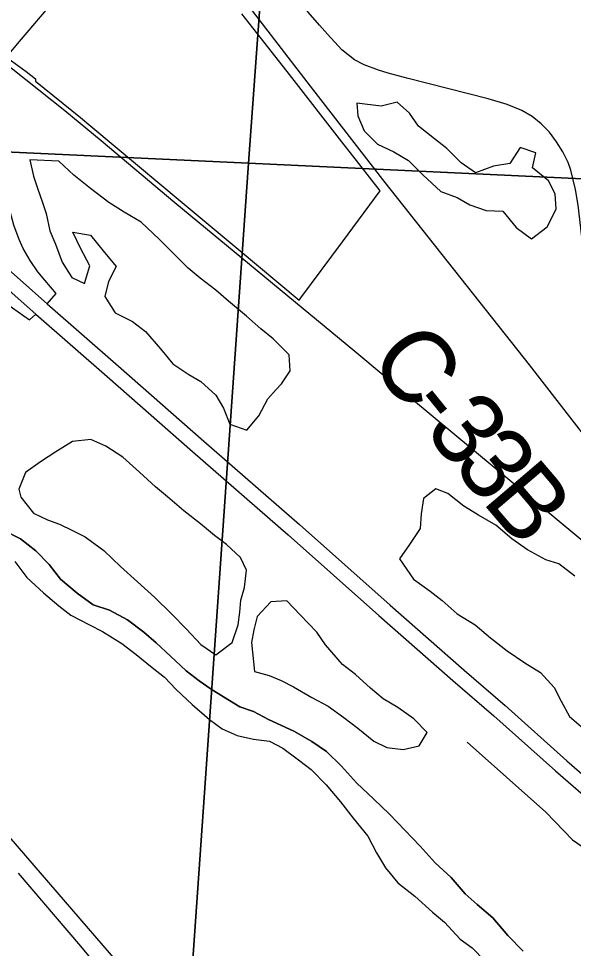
# Model space of a CAD drawing. Extents: x 39.8 to 73.8, y 13 to 35.
# Drawn here: x 44.259 to 44.694, y 30.521 to 31.251 of the extents above; entities that cross this region are included whole.
import ezdxf

# ---------------------------------------------------------------- set-up
doc = ezdxf.new("R2010")
doc.units = 0
for name, color, linetype in [('GM_X_Corporation', 7, 'Continuous'), ('GM_X_County_Road', 7, 'Continuous'), ('GM_X_County_Road_Text', 7, 'Continuous'), ('GM_X_Interchange_Ramps', 7, 'Continuous'), ('GM_X_Major_River', 7, 'Continuous'), ('GM_X_Minor_Lake', 7, 'Continuous'), ('GM_X_Rail_Line', 7, 'Continuous'), ('GM_X_State_Route', 7, 'Continuous'), ('GM_X_Township_Road', 7, 'Continuous'), ('GM_X_US_Route', 7, 'Continuous')]:
    doc.layers.add(name, color=color, linetype=linetype)

msp = doc.modelspace()

# ---------------------------------------------------------------- linework, layer by layer
at = {"layer": 'GM_X_Corporation'}
for points in [[(43.50363, 32.26026), (44.51605, 32.19572), (44.4392, 31.1377), (43.42824, 31.18464), (43.49688, 32.17123)], [(44.51605, 32.19572), (45.50689, 32.1262), (45.43139, 31.091), (44.4392, 31.1377)], [(44.4392, 31.1377), (44.36734, 30.10866), (43.36036, 30.17646), (43.42824, 31.18464)], [(45.43139, 31.091), (45.35678, 30.04923), (44.36734, 30.10866), (44.4392, 31.1377)]]:
    msp.add_lwpolyline(points, close=True, dxfattribs=at)
msp.add_lwpolyline([(44.17707, 31.26999), (44.23303, 31.23243), (44.26496, 31.20945), (44.27231, 31.20378), (44.27217, 31.20187), (44.30749, 31.17336), (44.31561, 31.16658), (44.38727, 31.10671), (44.43102, 31.07018), (44.47903, 31.0301), (44.48032, 31.03184), (44.51303, 31.076), (44.54253, 31.11582), (44.51915, 31.14584), (44.5144, 31.15194), (44.46948, 31.20962), (44.44265, 31.24369), (44.43396, 31.25472)], dxfattribs=at)
at = {"layer": 'GM_X_County_Road'}
for points in [[(44.25953, 31.23301), (44.2882, 31.26678), (44.30366, 31.27984), (44.31779, 31.28918), (44.33726, 31.29664), (44.35158, 31.30122), (44.36383, 31.30637), (44.37225, 31.31051), (44.38867, 31.31823)], [(44.44218, 31.25711), (44.48765, 31.1981), (44.54613, 31.12252), (44.65928, 30.97939), (44.71463, 30.90824), (44.72644, 30.89333), (44.75886, 30.855), (44.81526, 30.79658), (44.87483, 30.74254), (44.90837, 30.71525), (44.94666, 30.68662), (45.0573, 30.60034), (45.14776, 30.53069), (45.1864, 30.49736), (45.21018, 30.47485), (45.25625, 30.41816)], [(44.21891, 31.18513), (44.23311, 31.20197), (44.24725, 31.21855), (44.25953, 31.23301)], [(44.61064, 30.68328), (44.67255, 30.62834), (44.69344, 30.6067), (44.7068, 30.59748), (44.71696, 30.59428), (44.72881, 30.59033), (44.74085, 30.5845), (44.74894, 30.57791), (44.87201, 30.46877), (44.92544, 30.41816), (44.95724, 30.38297), (44.98791, 30.34666), (45.02367, 30.29961), (45.05979, 30.24561), (45.07504, 30.22002), (45.10608, 30.1647), (45.11907, 30.13967), (45.18154, 30.00363), (45.19396, 29.97672), (45.2075, 29.95264), (45.22124, 29.9342), (45.23479, 29.91726), (45.25379, 29.89788)]]:
    msp.add_lwpolyline(points, dxfattribs=at)
at = {"layer": 'GM_X_Interchange_Ramps'}
msp.add_lwpolyline([(44.28144, 31.02734), (44.2885, 31.03537), (44.27942, 31.04567), (44.27413, 31.05242), (44.26795, 31.06133), (44.26264, 31.07066), (44.25934, 31.0777), (44.25532, 31.0889), (44.25116, 31.10355), (44.24692, 31.11811), (44.24302, 31.13979), (44.2408, 31.15126), (44.23811, 31.15978), (44.23528, 31.16535), (44.22891, 31.17455), (44.22292, 31.18124), (44.21891, 31.18513)], dxfattribs=at)
at = {"layer": 'GM_X_Major_River'}
for p, q in [((44.26036, 30.84282), (44.24708, 30.8496)), ((44.27252, 30.83337), (44.26036, 30.84282)), ((44.28279, 30.82278), (44.27252, 30.83337)), ((44.25589, 30.82497), (44.26541, 30.81249)), ((44.29192, 30.81105), (44.28279, 30.82278)), ((44.26541, 30.81249), (44.27834, 30.80039)), ((44.30484, 30.80009), (44.29192, 30.81105)), ((44.27834, 30.80039), (44.2905, 30.79018)), ((44.31738, 30.79103), (44.30484, 30.80009)), ((44.2905, 30.79018), (44.3, 30.78301)), ((44.33027, 30.78689), (44.31738, 30.79103)), ((44.3, 30.78301), (44.31442, 30.77546)), ((44.34431, 30.77935), (44.33027, 30.78689)), ((44.31442, 30.77546), (44.32466, 30.77019)), ((44.35723, 30.76953), (44.34431, 30.77935)), ((44.32466, 30.77019), (44.33985, 30.76075)), ((44.36673, 30.76121), (44.35723, 30.76953)), ((44.33985, 30.76075), (44.35125, 30.75206)), ((44.37814, 30.75063), (44.36673, 30.76121)), ((44.35125, 30.75206), (44.36379, 30.74186)), ((44.3903, 30.73929), (44.37814, 30.75063)), ((44.36379, 30.74186), (44.37329, 30.7343)), ((44.40056, 30.73135), (44.3903, 30.73929)), ((44.37329, 30.7343), (44.38242, 30.72447)), ((44.41005, 30.72493), (44.40056, 30.73135)), ((44.38242, 30.72447), (44.39496, 30.71274)), ((44.41955, 30.71889), (44.41005, 30.72493)), ((44.43246, 30.71097), (44.41955, 30.71889)), ((44.39496, 30.71274), (44.40864, 30.70103)), ((44.44308, 30.70721), (44.43246, 30.71097)), ((44.45484, 30.70117), (44.44308, 30.70721)), ((44.40864, 30.70103), (44.41852, 30.69385)), ((44.4647, 30.69665), (44.45484, 30.70117)), ((44.47533, 30.69176), (44.4647, 30.69665)), ((44.41852, 30.69385), (44.43028, 30.68858)), ((44.43028, 30.68858), (44.44317, 30.68559)), ((44.48899, 30.68383), (44.47533, 30.69176)), ((44.44317, 30.68559), (44.45567, 30.68411)), ((44.45567, 30.68411), (44.46629, 30.67845)), ((44.50038, 30.6759), (44.48899, 30.68383)), ((44.46629, 30.67845), (44.47845, 30.66938)), ((44.51217, 30.66456), (44.50038, 30.6759)), ((44.47845, 30.66938), (44.48833, 30.66183)), ((44.48833, 30.66183), (44.50012, 30.64973)), ((44.52397, 30.65132), (44.51217, 30.66456)), ((44.53765, 30.63846), (44.52397, 30.65132)), ((44.50012, 30.64973), (44.51153, 30.63649)), ((44.51153, 30.63649), (44.52144, 30.62362)), ((44.54982, 30.62674), (44.53765, 30.63846)), ((44.52144, 30.62362), (44.53286, 30.60962)), ((44.56199, 30.61426), (44.54982, 30.62674)), ((44.57378, 30.60178), (44.56199, 30.61426)), ((44.53286, 30.60962), (44.53973, 30.59636)), ((44.58558, 30.58854), (44.57378, 30.60178)), ((44.53973, 30.59636), (44.54659, 30.58463)), ((44.59812, 30.5772), (44.58558, 30.58854)), ((44.54659, 30.58463), (44.55649, 30.5729)), ((44.55649, 30.5729), (44.56979, 30.56232)), ((44.60916, 30.56434), (44.59812, 30.5772)), ((44.61866, 30.55602), (44.60916, 30.56434)), ((44.56979, 30.56232), (44.58347, 30.54984)), ((44.63082, 30.54544), (44.61866, 30.55602)), ((44.58347, 30.54984), (44.59297, 30.54191)), ((44.59297, 30.54191), (44.60515, 30.52867)), ((44.64262, 30.53144), (44.63082, 30.54544)), ((44.60515, 30.52867), (44.61464, 30.52187)), ((44.65479, 30.51934), (44.64262, 30.53144)), ((44.61464, 30.52187), (44.62453, 30.51166))]:
    msp.add_line(p, q, dxfattribs=at)
for points in [[(44.24708, 30.8496), (44.26036, 30.84282), (44.27252, 30.83337), (44.28279, 30.82278), (44.29192, 30.81105), (44.30484, 30.80009), (44.31738, 30.79103), (44.33027, 30.78689), (44.34431, 30.77935), (44.35723, 30.76953), (44.36673, 30.76121), (44.37814, 30.75063), (44.3903, 30.73929), (44.40056, 30.73135), (44.41005, 30.72493), (44.41955, 30.71889), (44.43246, 30.71097), (44.44308, 30.70721), (44.45484, 30.70117), (44.4647, 30.69665), (44.47533, 30.69176), (44.48899, 30.68383), (44.50038, 30.6759), (44.51217, 30.66456), (44.52397, 30.65132), (44.53765, 30.63846), (44.54982, 30.62674), (44.56199, 30.61426), (44.57378, 30.60178), (44.58558, 30.58854), (44.59812, 30.5772), (44.60916, 30.56434), (44.61866, 30.55602), (44.63082, 30.54544), (44.64262, 30.53144), (44.65479, 30.51934)], [(44.25589, 30.82497), (44.26541, 30.81249), (44.27834, 30.80039), (44.2905, 30.79018), (44.3, 30.78301), (44.31442, 30.77546), (44.32466, 30.77019), (44.33985, 30.76075), (44.35125, 30.75206), (44.36379, 30.74186), (44.37329, 30.7343), (44.38242, 30.72447), (44.39496, 30.71274), (44.40864, 30.70103), (44.41852, 30.69385), (44.43028, 30.68858), (44.44317, 30.68559), (44.45567, 30.68411), (44.46629, 30.67845), (44.47845, 30.66938), (44.48833, 30.66183), (44.50012, 30.64973), (44.51153, 30.63649), (44.52144, 30.62362), (44.53286, 30.60962), (44.53973, 30.59636), (44.54659, 30.58463), (44.55649, 30.5729), (44.56979, 30.56232), (44.58347, 30.54984), (44.59297, 30.54191), (44.60515, 30.52867), (44.61464, 30.52187), (44.62453, 30.51166)]]:
    msp.add_lwpolyline(points, dxfattribs=at)
at = {"layer": 'GM_X_Minor_Lake'}
for p, q in [((44.52433, 31.18468), (44.52512, 31.17482)), ((44.54327, 31.18246), (44.52433, 31.18468)), ((44.55575, 31.18553), (44.54327, 31.18246)), ((44.56563, 31.17684), (44.55575, 31.18553)), ((44.57249, 31.16662), (44.56563, 31.17684)), ((44.52512, 31.17482), (44.5301, 31.16307)), ((44.5301, 31.16307), (44.54037, 31.15248)), ((44.58503, 31.1568), (44.57249, 31.16662)), ((44.59491, 31.14924), (44.58503, 31.1568)), ((44.54037, 31.15248), (44.55327, 31.14645)), ((44.60594, 31.13789), (44.59491, 31.14924)), ((44.65246, 31.1498), (44.64418, 31.13726)), ((44.66459, 31.14567), (44.65246, 31.1498)), ((44.26779, 31.14024), (44.2705, 31.12736)), ((44.29051, 31.13918), (44.26779, 31.14024)), ((44.55327, 31.14645), (44.56466, 31.13966)), ((44.56466, 31.13966), (44.57606, 31.12832)), ((44.66199, 31.1339), (44.66459, 31.14567)), ((44.3023, 31.12821), (44.29051, 31.13918)), ((44.61733, 31.12996), (44.60594, 31.13789)), ((44.63132, 31.13532), (44.61733, 31.12996)), ((44.64418, 31.13726), (44.63132, 31.13532)), ((44.67453, 31.1237), (44.66199, 31.1339)), ((44.2705, 31.12736), (44.27395, 31.11713)), ((44.31522, 31.11763), (44.3023, 31.12821)), ((44.57606, 31.12832), (44.59013, 31.11546)), ((44.32965, 31.10668), (44.31522, 31.11763)), ((44.67988, 31.11347), (44.67453, 31.1237)), ((44.27395, 31.11713), (44.2774, 31.10765)), ((44.59013, 31.11546), (44.60302, 31.11057)), ((44.60302, 31.11057), (44.61289, 31.10491)), ((44.68069, 31.10171), (44.67988, 31.11347)), ((44.2774, 31.10765), (44.28047, 31.09818)), ((44.3418, 31.09913), (44.32965, 31.10668)), ((44.61289, 31.10491), (44.62579, 31.1004)), ((44.28047, 31.09818), (44.28355, 31.08453)), ((44.35509, 31.0912), (44.3418, 31.09913)), ((44.62579, 31.1004), (44.63866, 31.10006)), ((44.63866, 31.10006), (44.64932, 31.0872)), ((44.67355, 31.08765), (44.67793, 31.09629)), ((44.67793, 31.09629), (44.68069, 31.10171)), ((44.36916, 31.07797), (44.35509, 31.0912)), ((44.28355, 31.08453), (44.28776, 31.07392)), ((44.30747, 31.07095), (44.30136, 31.08345)), ((44.30136, 31.08345), (44.31538, 31.08122)), ((44.31538, 31.08122), (44.32527, 31.06873)), ((44.64932, 31.0872), (44.6611, 31.07813)), ((44.6611, 31.07813), (44.67355, 31.08765)), ((44.28776, 31.07392), (44.29313, 31.0599)), ((44.39197, 31.05528), (44.36916, 31.07797)), ((44.31472, 31.05694), (44.30747, 31.07095)), ((44.32527, 31.06873), (44.33555, 31.05662)), ((44.29313, 31.0599), (44.30075, 31.04779)), ((44.31062, 31.04327), (44.31472, 31.05694)), ((44.33555, 31.05662), (44.32954, 31.04484)), ((44.40147, 31.04735), (44.39197, 31.05528)), ((44.30075, 31.04779), (44.31062, 31.04327)), ((44.32954, 31.04484), (44.32656, 31.03308)), ((44.41363, 31.0379), (44.40147, 31.04735)), ((44.42351, 31.02921), (44.41363, 31.0379)), ((44.32656, 31.03308), (44.33457, 31.0202)), ((44.43758, 31.01749), (44.42351, 31.02921)), ((44.33457, 31.0202), (44.34823, 31.01342)), ((44.44898, 31.00767), (44.43758, 31.01749)), ((44.34823, 31.01342), (44.35849, 31.00548)), ((44.35849, 31.00548), (44.37028, 30.99187)), ((44.45848, 30.99973), (44.44898, 31.00767)), ((44.47103, 30.98725), (44.45848, 30.99973)), ((44.37028, 30.99187), (44.3798, 30.98014)), ((44.47184, 30.97474), (44.47103, 30.98725)), ((44.3798, 30.98014), (44.39233, 30.97183)), ((44.39233, 30.97183), (44.40182, 30.96617)), ((44.46507, 30.96447), (44.47184, 30.97474)), ((44.40182, 30.96617), (44.41361, 30.95558)), ((44.461, 30.95992), (44.46507, 30.96447)), ((44.45451, 30.95268), (44.461, 30.95992)), ((44.41361, 30.95558), (44.41971, 30.94536)), ((44.44738, 30.93938), (44.45451, 30.95268)), ((44.41971, 30.94536), (44.42469, 30.93286)), ((44.43796, 30.92797), (44.44738, 30.93938)), ((44.42469, 30.93286), (44.43796, 30.92797)), ((44.31569, 30.92076), (44.3013, 30.91919)), ((44.32745, 30.91548), (44.31569, 30.92076)), ((44.3013, 30.91919), (44.28808, 30.91119)), ((44.34074, 30.9068), (44.32745, 30.91548)), ((44.28808, 30.91119), (44.276, 30.90318)), ((44.35366, 30.89508), (44.34074, 30.9068)), ((44.276, 30.90318), (44.2643, 30.8948)), ((44.2643, 30.8948), (44.25905, 30.88189)), ((44.36621, 30.88374), (44.35366, 30.89508)), ((44.25905, 30.88189), (44.2606, 30.87544)), ((44.37571, 30.8758), (44.36621, 30.88374)), ((44.58621, 30.88215), (44.5764, 30.87454)), ((44.59569, 30.87839), (44.58621, 30.88215)), ((44.60823, 30.86857), (44.59569, 30.87839)), ((44.2606, 30.87544), (44.2705, 30.86295)), ((44.38863, 30.86484), (44.37571, 30.8758)), ((44.5764, 30.87454), (44.57456, 30.86239)), ((44.2705, 30.86295), (44.2815, 30.85768)), ((44.40154, 30.85464), (44.38863, 30.86484)), ((44.57456, 30.86239), (44.57385, 30.85101)), ((44.61962, 30.8614), (44.60823, 30.86857)), ((44.2815, 30.85768), (44.29098, 30.85429)), ((44.63329, 30.85347), (44.61962, 30.8614)), ((44.29098, 30.85429), (44.30122, 30.84939)), ((44.30122, 30.84939), (44.31109, 30.84449)), ((44.41257, 30.84557), (44.40154, 30.85464)), ((44.57385, 30.85101), (44.56557, 30.83847)), ((44.64583, 30.84289), (44.63329, 30.85347)), ((44.31109, 30.84449), (44.32591, 30.83354)), ((44.42206, 30.83839), (44.41257, 30.84557)), ((44.65798, 30.8342), (44.64583, 30.84289)), ((44.32591, 30.83354), (44.33883, 30.82106)), ((44.43309, 30.82819), (44.42206, 30.83839)), ((44.56557, 30.83847), (44.55767, 30.82706)), ((44.6724, 30.82628), (44.65798, 30.8342)), ((44.43767, 30.81834), (44.43309, 30.82819)), ((44.55767, 30.82706), (44.56872, 30.81116)), ((44.68264, 30.82328), (44.6724, 30.82628)), ((44.33883, 30.82106), (44.35214, 30.80896)), ((44.69518, 30.81346), (44.68264, 30.82328)), ((44.43622, 30.80468), (44.4372, 30.81387)), ((44.4372, 30.81387), (44.43767, 30.81834)), ((44.56872, 30.81116), (44.58163, 30.80172)), ((44.35214, 30.80896), (44.36582, 30.79687)), ((44.43323, 30.79481), (44.43622, 30.80468)), ((44.36582, 30.79687), (44.37875, 30.78401)), ((44.58163, 30.80172), (44.59113, 30.79454)), ((44.43251, 30.78532), (44.43323, 30.79481)), ((44.45671, 30.79336), (44.44616, 30.78195)), ((44.46921, 30.79416), (44.45671, 30.79336)), ((44.47986, 30.78319), (44.46921, 30.79416)), ((44.59113, 30.79454), (44.60291, 30.78396)), ((44.37875, 30.78401), (44.39054, 30.77191)), ((44.43104, 30.77545), (44.43251, 30.78532)), ((44.49279, 30.76958), (44.47986, 30.78319)), ((44.60291, 30.78396), (44.61696, 30.77528)), ((44.42656, 30.7614), (44.43104, 30.77545)), ((44.44616, 30.78195), (44.44355, 30.77132)), ((44.61696, 30.77528), (44.62912, 30.76507)), ((44.39054, 30.77191), (44.40195, 30.75981)), ((44.44355, 30.77132), (44.4417, 30.76145)), ((44.49972, 30.75956), (44.49279, 30.76958)), ((44.41372, 30.75188), (44.42656, 30.7614)), ((44.4417, 30.76145), (44.44407, 30.7387)), ((44.62912, 30.76507), (44.64204, 30.75487)), ((44.40195, 30.75981), (44.41372, 30.75188)), ((44.51297, 30.74422), (44.49972, 30.75956)), ((44.64204, 30.75487), (44.65609, 30.74543)), ((44.44407, 30.7387), (44.45545, 30.7357)), ((44.52322, 30.73629), (44.51297, 30.74422)), ((44.65609, 30.74543), (44.66824, 30.73788)), ((44.45545, 30.7357), (44.46493, 30.73155)), ((44.46493, 30.73155), (44.47442, 30.72665)), ((44.53501, 30.7257), (44.52322, 30.73629)), ((44.66824, 30.73788), (44.67889, 30.72616)), ((44.47442, 30.72665), (44.48884, 30.71835)), ((44.54489, 30.71739), (44.53501, 30.7257)), ((44.67889, 30.72616), (44.68462, 30.71555)), ((44.48884, 30.71835), (44.50175, 30.71156)), ((44.55628, 30.7106), (44.54489, 30.71739)), ((44.50175, 30.71156), (44.5139, 30.7025)), ((44.56881, 30.70153), (44.55628, 30.7106)), ((44.68462, 30.71555), (44.69111, 30.70343)), ((44.5139, 30.7025), (44.52492, 30.69419)), ((44.69111, 30.70343), (44.70213, 30.69399)), ((44.57946, 30.69094), (44.56881, 30.70153)), ((44.52492, 30.69419), (44.53746, 30.68398)), ((44.57307, 30.6803), (44.57946, 30.69094)), ((44.53746, 30.68398), (44.5477, 30.67909)), ((44.56058, 30.67761), (44.57307, 30.6803)), ((44.5477, 30.67909), (44.56058, 30.67761))]:
    msp.add_line(p, q, dxfattribs=at)
at = {"layer": 'GM_X_Rail_Line'}
for points in [[(43.79656, 31.47428), (43.9305, 31.401), (43.98861, 31.36978), (44.10258, 31.30733), (44.14351, 31.28446), (44.21823, 31.23762), (44.25437, 31.21142), (44.29518, 31.17896), (44.32362, 31.15532), (44.38139, 31.1067), (44.52258, 30.99004), (44.56709, 30.95303)], [(44.73336, 29.38986), (44.70638, 29.45389), (44.6922, 29.50342), (44.68512, 29.54059), (44.68107, 29.57331), (44.67763, 29.61546), (44.66273, 29.91322), (44.66112, 29.98367), (44.6466, 30.05614), (44.61942, 30.12327), (44.57498, 30.20548), (44.5253, 30.28376), (44.46577, 30.36362), (44.36796, 30.47437), (44.05784, 30.83368), (43.97223, 30.93464), (43.91719, 30.99889)], [(44.56709, 30.95303), (44.72923, 30.81819), (45.01239, 30.58254), (45.10261, 30.50771), (45.19874, 30.42629), (45.20767, 30.41715), (45.22004, 30.40444), (45.2312, 30.39228), (45.24112, 30.38102), (45.26421, 30.3518), (45.57407, 29.92138), (45.66857, 29.79002), (45.71154, 29.73068), (45.7298, 29.70543), (45.75397, 29.67535), (45.79399, 29.62916), (45.86863, 29.54493), (45.96233, 29.44021), (46.06621, 29.3238)]]:
    msp.add_lwpolyline(points, dxfattribs=at)
at = {"layer": 'GM_X_State_Route'}
for points in [[(44.23293, 31.03678), (44.24967, 31.02728), (44.26743, 31.01461), (44.27253, 31.01924)], [(44.36207, 30.44721), (44.3542, 30.46233), (44.34275, 30.48014), (44.32811, 30.4986), (44.30775, 30.5232), (44.25881, 30.58045)]]:
    msp.add_lwpolyline(points, dxfattribs=at)
at = {"layer": 'GM_X_Township_Road'}
for points in [[(44.54891, 31.20831), (44.54109, 31.2105), (44.53007, 31.21477), (44.52244, 31.21861), (44.51239, 31.22664), (44.50118, 31.23871), (44.49498, 31.24589), (44.48602, 31.25618), (44.47162, 31.27257), (44.4377, 31.31324), (44.42724, 31.32476), (44.42005, 31.33267)], [(44.72566, 30.96451), (44.72296, 30.97121), (44.7185, 30.97932), (44.71422, 30.98762), (44.71118, 30.99643), (44.70929, 31.00558), (44.70367, 31.05508), (44.69784, 31.10455), (44.69582, 31.11694), (44.69203, 31.13208), (44.68994, 31.138), (44.68584, 31.14642), (44.68094, 31.15438), (44.67531, 31.16184), (44.66885, 31.16849), (44.66165, 31.17414), (44.65358, 31.17884), (44.64204, 31.18353), (44.62714, 31.18805), (44.56456, 31.20392), (44.54891, 31.20831)]]:
    msp.add_lwpolyline(points, dxfattribs=at)
at = {"layer": 'GM_X_US_Route'}
for points in [[(44.05154, 31.2294), (44.05875, 31.22309), (44.10958, 31.17852), (44.16846, 31.1264), (44.20614, 31.09396), (44.28144, 31.02734), (44.33741, 30.97832), (44.40419, 30.91943), (44.4792, 30.85396), (44.55027, 30.7908), (44.60833, 30.7398), (44.64058, 30.712), (44.68894, 30.66874), (44.72266, 30.63946), (44.78944, 30.58074), (44.84669, 30.53056), (44.8837, 30.4975)], [(44.14234, 31.13348), (44.15951, 31.11828), (44.16084, 31.11713), (44.19719, 31.08584), (44.27253, 31.01924), (44.32849, 30.97023), (44.39528, 30.91134), (44.47029, 30.84587), (44.54135, 30.7827), (44.59942, 30.73171), (44.63166, 30.70391), (44.68002, 30.66065), (44.71374, 30.63137), (44.78053, 30.57264), (44.83777, 30.52247), (44.87479, 30.48941)]]:
    msp.add_lwpolyline(points, dxfattribs=at)

# ---------------------------------------------------------------- texts
at = {"layer": 'GM_X_County_Road_Text'}
for s, rotation, p in [('C', 308.94506, (44.53226, 30.98246)), ('-', 308.964, (44.56161, 30.94614)), ('3', 308.99618, (44.57631, 30.92797)), ('3', 309.1499, (44.59843, 30.90064)), ('B', 310.47227, (44.62145, 30.8724))]:
    msp.add_text(s, height=0.05682, rotation=rotation, dxfattribs=at).set_placement(p)

doc.saveas('drawing.dxf')
